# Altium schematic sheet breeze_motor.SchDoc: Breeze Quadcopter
size A4; Author: myyerrol; Organization: Team MicroDynamics; Address1: NWPU; Address2: Xi'an; Address3: Shannxi; Address4: China; Revision: V0.1; SheetNumber: 2; SheetTotal: 5
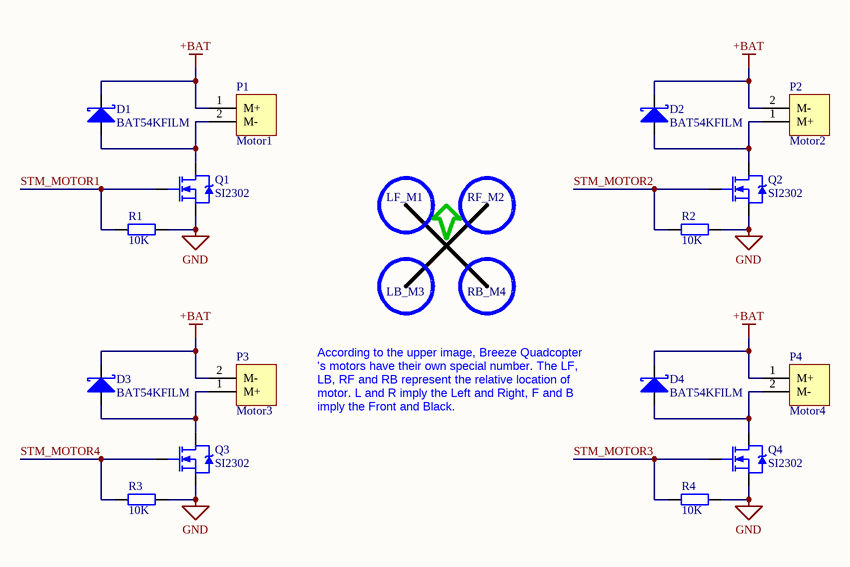
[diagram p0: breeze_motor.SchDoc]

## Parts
D1  BAT54KFILM  [SOD-523]
D2  BAT54KFILM  [SOD-523]
D3  BAT54KFILM  [SOD-523]
D4  BAT54KFILM  [SOD-523]
P1  Motor1  [HDRM-1X2]
P2  Motor2  [HDRM-1X2]
P3  Motor3  [HDRM-1X2]
P4  Motor4  [HDRM-1X2]
Q1  SI2302  [SOT-23]
Q2  SI2302  [SOT-23]
Q3  SI2302  [SOT-23]
Q4  SI2302  [SOT-23]
R1  value 10K  [SMD-0603]  (hidden comment: RES-0603)
R2  value 10K  [SMD-0603]  (hidden comment: RES-0603)
R3  value 10K  [SMD-0603]  (hidden comment: RES-0603)
R4  value 10K  [SMD-0603]  (hidden comment: RES-0603)

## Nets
+BAT: D1.2(K) D2.2(K) D3.2(K) D4.2(K) P1.1(M+) P2.2(M-) P3.2(M-) P4.1(M+)
GND: Q1.2(S) Q2.2(S) Q3.2(S) Q4.2(S) R1.2 R2.2 R3.2 R4.2
STM_MOTOR1: Q1.1(G) R1.1
STM_MOTOR2: Q2.1(G) R2.1
STM_MOTOR3: Q4.1(G) R4.1
STM_MOTOR4: Q3.1(G) R3.1
NetD1_1: D1.1(A) P1.2(M-) Q1.3(D)
NetD2_1: D2.1(A) P2.1(M+) Q2.3(D)
NetD3_1: D3.1(A) P3.1(M+) Q3.3(D)
NetD4_1: D4.1(A) P4.2(M-) Q4.3(D)

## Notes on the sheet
- LF_M1
- RF_M2
- LB_M3
- RB_M4
- According to the upper image, Breeze Quadcopter 's motors have their own special number. The LF, LB, RF and RB represent the relative location of motor. L and R imply the Left and Right, F and B  imply the Front and Black.

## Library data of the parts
D1-D4 = BAT54KFILM: Schottky Diode
P1 P4 = Motor_A: Motor Header
P2 P3 = Motor_B: Motor Header
Q1-Q4 = SI2302: N-Channel Enhancement Mode Field Effect Transistor
R1-R4 = RES-0603: Resistor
